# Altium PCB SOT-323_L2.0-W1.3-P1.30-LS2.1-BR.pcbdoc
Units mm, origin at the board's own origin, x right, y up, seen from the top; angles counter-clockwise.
Board outline 15.2 x 15.35 mm, 2 copper layers (Top Layer, Bottom Layer), stack 0 mm thick; 1 components, 0 nets, 3 pads, 0 vias.
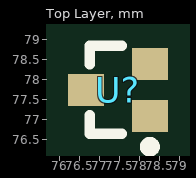
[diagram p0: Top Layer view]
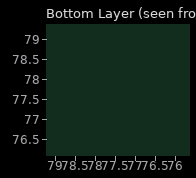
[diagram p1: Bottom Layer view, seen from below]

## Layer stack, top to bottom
Top Layer: signal copper (thickness not stored)
Bottom Layer: signal copper (thickness not stored)

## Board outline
85.05,69.85 69.85,69.85 69.85,85.199 85.05,85.199

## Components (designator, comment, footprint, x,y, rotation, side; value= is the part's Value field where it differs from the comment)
U? "" SOT-323_L2.0-W1.3-P1.30-LS2.1-BR 77.45,77.749 r0 top

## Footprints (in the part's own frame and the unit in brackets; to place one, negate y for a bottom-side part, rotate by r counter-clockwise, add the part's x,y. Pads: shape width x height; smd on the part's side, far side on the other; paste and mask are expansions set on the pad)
SOT-323_L2.0-W1.3-P1.30-LS2.1-BR [mm]
  rect 0.9x0.8 smd: 1(0.8,-0.65) 2(0.8,0.65) 3(-0.8,0)
  silkscreen extent -0.7,-1.55 0.93,1.1

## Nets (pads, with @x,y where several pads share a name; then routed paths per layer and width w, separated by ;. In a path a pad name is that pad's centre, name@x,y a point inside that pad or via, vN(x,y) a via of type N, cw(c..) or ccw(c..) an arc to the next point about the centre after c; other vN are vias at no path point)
pads on no net: U?.1 U?.2 U?.3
